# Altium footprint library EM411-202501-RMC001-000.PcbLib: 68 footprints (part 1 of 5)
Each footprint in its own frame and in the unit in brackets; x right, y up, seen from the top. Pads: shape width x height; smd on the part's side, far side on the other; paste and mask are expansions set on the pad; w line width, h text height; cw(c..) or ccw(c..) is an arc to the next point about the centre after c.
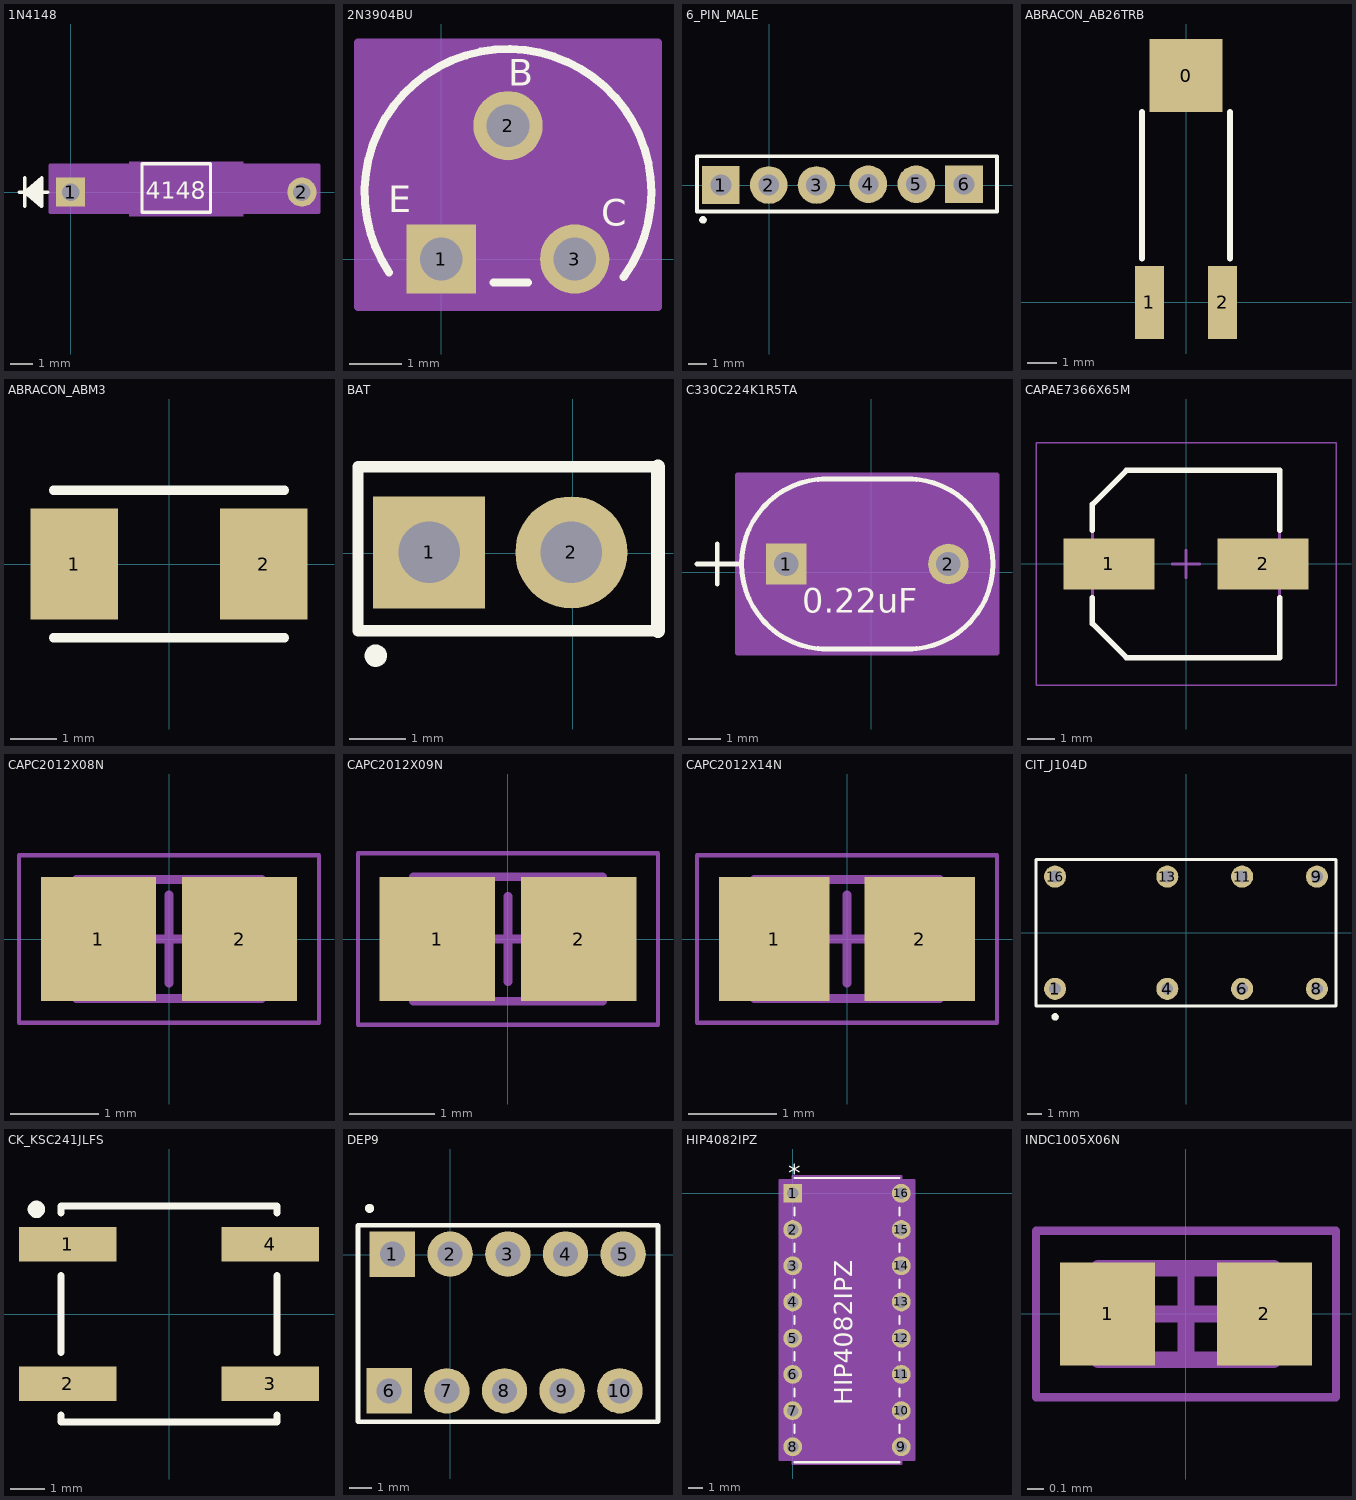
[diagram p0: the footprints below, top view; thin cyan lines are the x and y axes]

## 1N4148 [mil]
pads (2):
  rect 51x51 hole 31 paste-99999 mask+0: 1(0,0)
  round 51 hole 31 paste-99999 mask+0: 2(405,0)
Top Overlay:
  lines w6: -90.5,0 -40.5,0 ; -80.5,-25 -80.5,25 ; -50.5,-20 -80.5,0 ; -50.5,-15 -80.5,0 ; -50.5,-10 -80.5,0 ; -50.5,-5 -80.5,0 ; -50.5,5 -80.5,0 ; -50.5,10 -80.5,0 ; -50.5,15 -80.5,0 ; -50.5,20 -80.5,0 ; -80.5,0 -50.5,-25 -50.5,25 -80.5,0 ; 125,-35 125,50 245,50 245,-35 125,-35
  text "4148" at 131.67,-11.38 h30
Mechanical 13:
  lines w1: -90.5,0 -40.5,0 ; -80.5,-25 -80.5,25 ; -50.5,-20 -80.5,0 ; -50.5,-15 -80.5,0 ; -50.5,-10 -80.5,0 ; -50.5,-5 -80.5,0 ; -50.5,5 -80.5,0 ; -50.5,10 -80.5,0 ; -50.5,15 -80.5,0 ; -50.5,20 -80.5,0 ; 0,0 105,0 ; 104.66,-32.05 104.66,42.95 ; 256,-32.5 256,42.5 ; 263,0 405,0 ; -80.5,0 -50.5,-25 -50.5,25 -80.5,0
Mechanical 15:
  region: 102.5,-37 -32.5,-37 -32.5,45 102.5,45 102.5,53 302.5,53 302.5,48 435,48 435,-37 302.5,-37 302.5,-42 102.5,-42
  lines w6: -35.5,-35.5 435,-35.5 435,47.5 -35.5,47.5 -35.5,-35.5

## 2N3904BU [mil]
pads (3):
  rect 52x52 hole 32 paste-99999 mask+0: 1(0,0)
  round 52 hole 32 paste-99999 mask+0: 2(50,100) 3(100,0)
Top Overlay:
  lines w6: -39.1,-10.15 cw(c50,50) 157.5,50 cw(c50,50) 136.65,-13.63 ; 39.1,-17.5 65.03,-17.5
  text "E" at -40,35 h20
  text "B" at 50,130 h20
  text "C" at 120,25 h20
Mechanical 13:
  circle w1: c-42.5,0 r5
  lines w1: -31.24,-12.5 cw(c50,50) 131.24,-12.5 -31.24,-12.5
  lines w6: -10,0 10,0 ; 0,-10 0,10
Mechanical 15:
  region: 162.5,-36 -62.5,-36 -62.5,162.5 162.5,162.5
  lines w6: -62.5,-36 -62.5,162.5 162.5,162.5 162.5,-36 -62.5,-36
3D body "TO-92_FAS.step": height 290, standoff -107.99, extent -52.39,-10.98 152.39,152.04

## 6_PIN_MALE [mm]
pads (6):
  rect 2x2 hole 1.1: 1(-2.565,0.017) 6(10.35,0.065)
  round 2 hole 1.1: 2(-0.025,0.017) 3(2.515,0.017) 4(5.27,0.065) 5(7.81,0.065)
Top Overlay:
  circle w0.2: c-3.516,-1.829 r0.1
  lines w0.2: -3.835,-1.384 -3.835,1.546 12.102,1.546 12.102,-1.384 -3.835,-1.384
3D body "TSW-103-07-G-S.stp": height 8.41, standoff -2.51, extent -3.962,-1.253 3.785,1.287
3D body "TSW-103-07-G-S.stp": height 8.41, standoff -2.51, extent 4.002,-1.186 11.749,1.354

## ABRACON_AB26TRB [mm] "Low Frequency Reflowable Cylindrical Watch Crystal"
height 2.5
pads (3):
  rect 2.5x2.5 smd: 0(0,7.75)
  rect 1x2.5 smd: 1(-1.25,0) 2(1.25,0)
Top Overlay:
  lines w0.2: -1.5,1.5 -1.5,6.5 ; 1.5,1.5 1.5,6.5
3D body "AB26TRB.STEP": height 2.25, standoff 0.03, extent -1.42,-1 1.42,8

## ABRACON_ABM3 [mm] "Ceramic SMD Crystal"
height 1.3
pads (2):
  rect 1.9x2.4 smd: 1(-2.05,0) 2(2.05,0)
Top Overlay:
  lines w0.2: -2.5,-1.6 2.5,-1.6 ; -2.5,1.6 2.5,1.6
3D body "ABM3.STEP": height 1.35, standoff 0.05, extent -2.5,-1.6 2.5,1.6

## BAT [mm]
pads (2):
  rect 2x2 hole 1.1: 1(-2.565,0.017)
  round 2 hole 1.1: 2(-0.025,0.017)
Top Overlay:
  circle w0.2: c-3.516,-1.829 r0.1
  lines w0.2: 1.524,-1.384 0.149,-1.384 -3.835,-1.384 -3.835,1.546 1.524,1.546
  lines w0.254: 1.524,-1.384 1.524,1.546

## C330C224K1R5TA [mil] "0.22 µF ±10% 100V Ceramic Capacitor X7R Radial"
pads (2):
  rect 50x50 hole 30 paste-99999 mask-25: 1(-105,10)
  round 50 hole 30 paste-99999 mask-25: 2(95,10)
Top Overlay:
  lines w6: -215,10 -165,10 ; -190,-15 -190,35 ; -60,-95 50,-95 ; -60,115 50,115 ; -55,-95 cw(c-55,10) -55,115 ; 45,-95 ccw(c45,10) 150,10 ccw(c45,10) 45,115
  text "0.22uF" at -85,-50 h30
Mechanical 13:
  lines w1: -215,10 -165,10 ; -190,-15 -190,35 ; -55,-90 cw(c-55,10) -55,110 45,110 cw(c45,10) 45,-90 -55,-90
Mechanical 15:
  region: 155,-100 -165,-100 -165,120 155,120
  lines w6: -165,-100 -165,120 155,120 155,-100 -165,-100
3D body "CAP_C330_KEM.step": height 410, standoff -110, extent -165,-75 135,125

## CAPAE7366X65M [mm] "Aluminum Electrolytic Capacitor, Body 6.60x6.60x6.50mm, IPC Low Density"
height 6.5
pads (2):
  rect 3.3x1.85 smd: 1(-2.8,0) 2(2.8,0)
Top Overlay:
  lines w0.2: -3.4,-1.225 -3.4,-2.163 -2.163,-3.4 3.4,-3.4 3.4,-1.225 ; -3.4,1.225 -3.4,2.163 -2.163,3.4 3.4,3.4 3.4,1.225
Top Courtyard:
  lines w0.05: -5.45,-4.4 -5.45,4.4 5.45,4.4 5.45,-4.4 -5.45,-4.4
  lines w0.1: -0.5,0 0.5,0 ; 0,-0.5 0,0.5
Mechanical 13:
  lines w0.1: -3.4,-2.163 -2.163,-3.4 3.4,-3.4 3.4,3.4 -2.163,3.4 -3.4,2.163 -3.4,-2.163
3D body "CAPAE7366X65M.step": height 6.5, standoff 0, extent -3.65,-3.4 3.65,3.4

## CAPC2012X08N [mm] "Chip Capacitor, 2-Leads, Body 2.00x1.25mm, IPC Medium Density"
height 0.75
pads (2):
  rect 1.3x1.4 smd: 1(-0.8,0) 2(0.8,0)
Top Courtyard:
  lines w0.05: -1.7,-0.95 1.7,-0.95 1.7,0.95 -1.7,0.95 -1.7,-0.95
  lines w0.1: -0.5,0 0.5,0 ; 0,-0.5 0,0.5
Mechanical 13:
  lines w0.1: -1.05,-0.675 1.05,-0.675 1.05,0.675 -1.05,0.675 -1.05,-0.675
3D body "CAPC2012X08N.step": height 0.75, standoff 0, extent -1.05,-0.675 1.05,0.675

## CAPC2012X09N [mm] "Chip Capacitor, 2-Leads, Body 2.00x1.25mm, IPC Medium Density"
height 0.94
pads (2):
  rect 1.35x1.45 smd: 1(-0.825,0) 2(0.825,0)
Mechanical 13:
  lines w0.1: -1.105,-0.725 -1.105,0.725 1.105,0.725 1.105,-0.725 -1.105,-0.725
Mechanical 15:
  lines w0.05: -1.75,-1 -1.75,1 1.75,1 1.75,-1 -1.75,-1
  lines w0.1: -0.5,0 0.5,0 ; 0,-0.5 0,0.5
3D body "CAPC2012X09N.step": height 0.94, standoff 0, extent -1.105,-0.725 1.105,0.725

## CAPC2012X14N [mm] "Chip Capacitor, 2-Leads, Body 2.00x1.25mm, IPC Medium Density"
height 1.35
pads (2):
  rect 1.25x1.4 smd: 1(-0.825,0) 2(0.825,0)
Top Courtyard:
  lines w0.05: -1.7,-0.95 1.7,-0.95 1.7,0.95 -1.7,0.95 -1.7,-0.95
  lines w0.1: -0.5,0 0.5,0 ; 0,-0.5 0,0.5
Mechanical 13:
  lines w0.1: -1.05,-0.675 1.05,-0.675 1.05,0.675 -1.05,0.675 -1.05,-0.675
3D body "CAPC2012X14N.step": height 1.35, standoff 0, extent -1.05,-0.675 1.05,0.675

## CIT_J104D [mm] "Dual Form C Signal Relay"
height 11.1
pads (8):
  round 1.5 hole 0.8: 1(-8.89,-3.81) 4(-1.27,-3.81) 6(3.81,-3.81) 8(8.89,-3.81) 9(8.89,3.81) 11(3.81,3.81) 13(-1.27,3.81) 16(-8.89,3.81)
Top Overlay:
  circle w0.25: c-8.89,-5.715 r0.125
  lines w0.2: -10.185,-4.985 -10.185,4.985 10.185,4.985 10.185,-4.985 -10.185,-4.985
3D body "c-2-1393793-1-c1-3d.stp": height 10.5, standoff -3.5, extent -10.1,-5 10.1,5

## CK_KSC241JLFS [mm] "KSC2 Series Sealed Tact Switch for SMT"
height 2.9
pads (4):
  rect 2.8x1 smd: 1(-2.9,2) 2(-2.9,-2) 3(2.9,-2) 4(2.9,2)
Top Overlay:
  circle w0.25: c-3.8,3 r0.125
  lines w0.2: -3.1,-2.9 -3.1,-3.1 3.1,-3.1 3.1,-2.9 ; -3.1,-1.1 -3.1,1.1 ; -3.1,2.9 -3.1,3.1 3.1,3.1 3.1,2.9 ; 3.1,-1.1 3.1,1.1
3D body "KSC241JLFS.stp": height 3.55, standoff 0.05, extent -3.4,-3.15 3.4,3.15

## DEP9 [mm]
pads (10):
  rect 2x2 hole 1.1: 1(-2.548,0.023) 6(-2.696,-5.997)
  round 2 hole 1.1: 2(-0.008,0.023) 3(2.532,0.023) 4(5.072,0.023) 5(7.612,0.023) 7(-0.156,-5.997) 8(2.384,-5.997) 9(4.924,-5.997) 10(7.464,-5.997)
Top Overlay:
  circle w0.2: c-3.556,2.032 r0.1
  lines w0.2: 2.667,1.293 9.144,1.293 9.144,0.752 9.144,-0.331 9.144,-0.872 9.144,-5.201 9.144,-7.366 -4.064,-7.366 -4.064,1.293 -1.278,1.293 3.802,1.293
3D body "61300411121.stp": height 7.27, standoff -4.27, extent -3.937,-7.293 6.223,-4.753
3D body "61300411121.stp": height 8.59, standoff -2.95, extent -3.818,-1.247 6.342,1.293

## HIP4082IPZ [mil]
pads (16):
  rect 52x52 hole 32 paste-99999 mask+0: 1(0,0)
  round 52 hole 32 paste-99999 mask+0: 2(0,-100) 3(0,-200) 4(0,-300) 5(0,-400) 6(0,-500) 7(0,-600) 8(0,-700) 9(300,-700) 10(300,-600) 11(300,-500) 12(300,-400) 13(300,-300) 14(300,-200) 15(300,-100) 16(300,0)
Top Overlay:
  lines w6: 5,-742.5 295,-742.5 ; 5,-661.22 5,-638.78 ; 5,-561.22 5,-538.78 ; 5,-461.22 5,-438.78 ; 5,-361.22 5,-338.78 ; 5,-261.22 5,-238.78 ; 5,-161.22 5,-138.78 ; 5,-61.22 5,-39.1 ; 5,42.5 295,42.5 ; 295,-661.22 295,-638.78 ; 295,-561.22 295,-538.78 ; 295,-461.22 295,-438.78 ; 295,-361.22 295,-338.78 ; 295,-261.22 295,-238.78 ; 295,-161.22 295,-138.78 ; 295,-61.22 295,-38.78
  text "HIP4082IPZ" at 165,-585 h50
  text "*" at -12.5,31 h50
Mechanical 13:
  lines w1: 138,37.5 ccw(c150,37.5) 162,37.5 ; -16,-716 10,-716 10,-684 -16,-684 -16,-716 ; -16,-616 10,-616 10,-584 -16,-584 -16,-616 ; -16,-516 10,-516 10,-484 -16,-484 -16,-516 ; -16,-416 10,-416 10,-384 -16,-384 -16,-416 ; -16,-316 10,-316 10,-284 -16,-284 -16,-316 ; -16,-216 10,-216 10,-184 -16,-184 -16,-216 ; -16,-116 10,-116 10,-84 -16,-84 -16,-116 ; -16,-16 10,-16 10,16 -16,16 -16,-16 ; 10,-737.5 10,37.5 290,37.5 290,-737.5 10,-737.5 ; 290,-716 316,-716 316,-684 290,-684 290,-716 ; 290,-616 316,-616 316,-584 290,-584 290,-616 ; 290,-516 316,-516 316,-484 290,-484 290,-516 ; 290,-416 316,-416 316,-384 290,-384 290,-416 ; 290,-316 316,-316 316,-284 290,-284 290,-316 ; 290,-216 316,-216 316,-184 290,-184 290,-216 ; 290,-116 316,-116 316,-84 290,-84 290,-116 ; 290,-16 316,-16 316,16 290,16 290,-16
  text "*" at 7.5,-25 h50
Mechanical 15:
  region: 300,-736 336,-736 336,36 300,36 300,47.5 0,47.5 0,36 -36,36 -36,-736 0,-736 0,-747.5 300,-747.5
  lines w6: -36,-736 0,-736 0,-747.5 300,-747.5 300,-736 336,-736 336,36 300,36 300,47.5 0,47.5 0,36 -36,36 -36,-736
3D body "PDIP16_REN.step": height 215.12, standoff -100, extent -5,-737.48 315,37.48

## INDC1005X06N [mm] "Chip Inductor, 2-Leads, Body 1.00x0.50mm, IPC Medium Density"
height 0.55
pads (2):
  rect 0.57x0.62 smd: 1(-0.47,0) 2(0.47,0)
Top Courtyard:
  lines w0.05: -0.9,-0.5 -0.9,0.5 0.9,0.5 0.9,-0.5 -0.9,-0.5
  lines w0.1: -0.275,0 0.275,0 ; 0,-0.275 0,0.275
Mechanical 13:
  lines w0.1: -0.525,-0.275 -0.525,0.275 0.525,0.275 0.525,-0.275 -0.525,-0.275
3D body "INDC1005X06N.step": height 0.55, standoff 0, extent -0.525,-0.275 0.525,0.275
